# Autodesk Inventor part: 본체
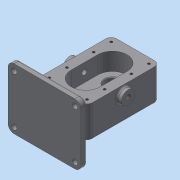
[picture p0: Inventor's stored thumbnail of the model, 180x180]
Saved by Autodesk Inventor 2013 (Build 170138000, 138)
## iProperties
Created: 2020-04
Part Number: 본체
Material: 일반
Document SubType Name: Modeling
Designer: dgall
Density: 1 g/cm^3
Author: dgall
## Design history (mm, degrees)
sketch "스케치1"
  geometry: L1 (-40, 60)-(40, 60); L2 (40, 60)-(40, -60); L3 (40, -60)-(-40, -60); L4 (-40, -60)-(-40, 60); 3 further points
  constraints: 8 end point, 2 midpoint, 2 parallel, 1 horizontal, 1 horizontal alignment, 1 perpendicular, 1 vertical alignment
  dimensions: "d0" = 120 distance of L1.end L2.end; "d2" = 80 distance of L1.start L1.end
extrude "돌출1" new body sketch "스케치1" distance "d3" = 53; taper "d4" = 0 deg
sketch "스케치2"
  geometry: L1 (40, -60)-(40, 60) reference; L2 (-24, 22)-(-24, -22); L3 (24, -22)-(24, 22); A1 r 24 centre (0, -22) between (-24, -22) and (24, -22); A2 r 24 centre (0, 22) between (24, 22) and (-24, 22); 1 further point
  constraints: 4 end point, 4 point on circle, 4 tangent, 2 centre point, 2 parallel, 2 vertical alignment
  dimensions: "d5" = 44 distance of L3.start L3.end; "d7" = 24 radius of A2; "d8" = 22 distance of point (0, 0) A2.centre
extrude "돌출2" cut sketch "스케치2" distance "d9" = 29; taper "d10" = 0 deg
sketch "스케치3"
  geometry: L1 (40, 60)-(-40, 60) reference; C1 r 19 at (0, 22); 1 further point
  constraints: 1 centre point, 1 vertical alignment
  dimensions: "d11" = 38 diameter of C1; "d13" = 38 distance from line of C1.centre L1
sketch "스케치4"
  geometry: L1 (-40, 60)-(40, 60) reference; L2 (40, 60)-(40, -60) reference; L3 (40, -60)-(-40, -60) reference; L4 (-40, -60)-(-40, 60) reference; C1 r 19 at (0, 22) reference; C2 r 12.5 at (0, 22); 1 further point
  constraints: 1 centre point, 1 coincident
  dimensions: "d16" = 25 diameter of C2
extrude "돌출4" cut sketch "스케치4" distance "d18" = 15; taper "d19" = 0 deg
sketch "스케치5"
  geometry: L1 (8, -17)-(46, -17) reference; L2 (38.404, -17)-(38, -16.3); L3 (38, -16.3)-(38, -9.7); L4 (38, -9.7)-(24, -9.7); L5 (24, -9.7)-(24, -17); L6 (9.5, 24)-(34.5, 24) reference; L7 (60, 0)-(60, 53) reference; 1 further point
  constraints: 8 end point, 3 perpendicular, 2 point on line
  dimensions: "d20" = 7.3 distance between parallel lines of L1 L4; "d21" = 0.7 vertical distance of L2.start L2.end; "d22" = 30 deg angle of L3 L2; "d23" = 36 distance from line of L4.end L7; "d24" = 28 diameter of L3 L5
revolve "회전1" sketch "스케치5" stored, may be unused: angle "d25" = 90 deg
sketch "스케치7"
  geometry: L1 (0, 120)-(0, 0) reference; L2 (-53, 0)-(-53, 120) reference; C1 r 11 at (-39, 60); 2 further points
  constraints: 1 centre point, 1 horizontal alignment, 1 midpoint
  dimensions: "d30" = 22 diameter of C1; "d32" = 14 distance from line of C1.centre L2
extrude "돌출6" join sketch "스케치7" distance "d33" = 8; taper "d34" = 0 deg
hole "구멍1" diameter "d37" = 8.376; stored, may be unused: countersink angle "d41" = 90 deg, drill point angle "d43" = 118 deg; dims "d38" = 10, "d39" = 4, "d40" = 2, "d42" = 8, "d136" = 10, "d137" = 10
sketch "스케치8"
  geometry: L1 (60, 0)-(60, 53) reference; L2 (-80, 83)-(-90, 83); L3 (-90, 83)-(-90, -17); L4 (-90, -17)-(-80, -17); L5 (-80, -17)-(-80, 83); L6 (46, 0)-(46, -17) reference; C1 r 4.188 at (0, 39) reference; 1 further point
  constraints: 8 end point, 2 parallel, 1 horizontal, 1 horizontal alignment, 1 perpendicular
  dimensions: "d50" = 100 distance of L2.end L3.end; "d52" = 10 distance of L3.end L4.end; "d53" = 90 distance from line of L3 C1.centre
extrude "돌출7" join sketch "스케치8" stored distance "d54" = 120; taper "d55" = 0 deg
sketch "스케치9"
  geometry: L1 (-40, 60)-(-40, -60) reference; 5 further points
  constraints: 2 horizontal alignment, 2 vertical alignment
  dimensions: "d56" = 22 vertical distance of point (0, 0) point (31, 22); "d57" = 29 distance of point (31, 22) point (31, 51); "d58" = 62 distance of point (-31, 51) point (31, 51); "d59" = 9 distance from line of L1 point (-31, 51)
hole "구멍2" sketch "스케치9" at (-31, 51), (-31, 22), (31, 51), (31, 22) diameter "d60" = 4.134; stored, may be unused: countersink angle "d64" = 90 deg, drill point angle "d66" = 118 deg; dims "d61" = 10, "d62" = 4, "d63" = 2, "d65" = 12
fillet "모깎기1" dims "d67" = 9
fillet "모깎기2" dims "d68" = 10
sketch "스케치10"
  geometry: A1 r 10 centre (0, 90) between (0, 100) and (-10, 90) reference; A2 r 10 centre (0, 10) between (-10, 10) and (0, 0) reference; A3 r 10 centre (100, 90) between (110, 90) and (100, 100) reference; A4 r 10 centre (100, 10) between (100, 0) and (110, 10) reference; 5 further points
  constraints: 4 coincident
hole "구멍3" sketch "스케치10" at (0, 90), (100, 90), (100, 10), (0, 10) diameter "d69" = 9; stored, may be unused: countersink angle "d73" = 90 deg, drill point angle "d75" = 0 deg; dims "d70" = 10, "d71" = 4, "d72" = 2, "d74" = 12
sketch "스케치12"
  geometry: L1 (-51, 53)-(-60, 53) reference; L2 (-60, 53)-(-60, 0) reference; L3 (-60, 0)-(-51, 0) reference; L4 (-51, 0)-(-51, 53) reference; L5 (-80, -7)-(-80, 73) reference; L6 (-80, -7)-(-80, -17) reference; L7 (-80, 83)-(-80, 73) reference; L8 (-60, 0)-(-60, 53) reference; L9 (-60, 11.547)-(-80, 0); L10 (-60, 41.453)-(-80, 53); 1 further point
  constraints: 4 end point, 4 point on line
  dimensions: "d84" = 17 distance of L6.end L9.end; "d85" = 53 distance of L10.end L9.end; "d86" = 60 deg angle of L5 L10; "d87" = 60 deg angle of L5 L9
  node "투영된 루프3"
fillet "모깎기3" dims "d88" = 3
extrude "돌출9" join sketch "스케치12" stored distance "d89" = 48; taper "d90" = 0 deg
fillet "모깎기4" dims "d91" = 3
fillet "모깎기5" dims "d92" = 3
fillet "모깎기6" dims "d93" = 3
fillet "모깎기7" dims "d94" = 3
chamfer "모따기1" distance "d97" = 1; stored, may be unused: second distance "d98" = 2, angle "d99" = 45 deg
sketch "스케치13"
  geometry: L1 (-10, -7)-(-10, -87) reference; L2 (0, -97)-(100, -97) reference; 2 further points
  constraints: 1 other
  dimensions: "d100" = 60 distance from line of L1 point (50, -87); "d101" = 10 distance from line of L2 point (50, -87)
feature "엠보싱1" sketch "스케치13" dims "d0" = 120, "d2" = 80, "d102" = 0.5, "d103" = 0
extrude "돌출10" join sketch "스케치3" distance "d104" = 17; taper "d105" = 0 deg
fillet "모깎기10" dims "d120" = 3
sketch "스케치16"
  geometry: L1 (3, -17)-(41, -17) reference; L2 (36.404, -17)-(36, -16.3); L3 (36, -16.3)-(36, -9.7); L4 (36, -9.7)-(22, -9.7); L5 (22, -9.7)-(22, -17); L6 (36.404, -17)-(22, -17); L7 (60, 53)-(60, 3) reference; 1 further point
  constraints: 10 end point, 3 perpendicular, 1 collinear, 1 midpoint, 1 point on line
  dimensions: "d122" = 30 deg angle of L3 L2; "d123" = 0.7 vertical distance of L2.start L2.end; "d125" = 38 distance from line of L7 L4.end; "d126" = 28 diameter of L3 L5; "d127" = 7.3 distance between parallel lines of L1 L4
revolve "회전3" sketch "스케치16" stored, may be unused: angle "d128" = 90 deg
sketch "스케치17"
  geometry: C1 r 14 at (0, 0) reference; C2 r 8.5 at (0, 0); 1 further point
  constraints: 1 centre point, 1 coincident
  dimensions: "d129" = 17 diameter of C2
extrude "돌출12" cut sketch "스케치17" stored distance "d131" = 17; taper "d132" = 0 deg
fillet "모깎기12" dims "d133" = 0.5
node "솔리드1"
mirror "대칭1"
mirror "대칭2"
mirror "대칭3"
node "투영된 루프1"
